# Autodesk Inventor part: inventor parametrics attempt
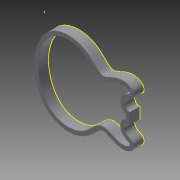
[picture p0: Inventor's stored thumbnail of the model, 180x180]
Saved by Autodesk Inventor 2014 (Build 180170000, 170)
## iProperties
Created: 2015-02
Part Number: inventor parametrics attempt
Material: Generic
Document SubType Name: Modeling
Designer: 11084370
Density: 1 g/cm^3
Appearance: Default
Author: 11084370
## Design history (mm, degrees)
sketch "Sketch1"
  geometry: L1 (-473.76, -224.836)-(-469.826, -225.36); L2 (-469.826, -225.36)-(-462.898, -226.026); L3 (-462.898, -226.026)-(-453.887, -232.464); L4 (-453.887, -232.464)-(-448.305, -241.852); L5 (-448.305, -241.852)-(-447.134, -252.797); L6 (-447.134, -252.797)-(-450.098, -262.975); L7 (-450.098, -262.975)-(-457.24, -271.275); L8 (-457.24, -271.275)-(-466.686, -277.144); L9 (-466.686, -277.144)-(-477.1, -282.087); L10 (-477.1, -282.087)-(-486.72, -288.007); L11 (-486.72, -288.007)-(-494.372, -297.815); L12 (-494.372, -297.815)-(-495.528, -309.852); L13 (-495.528, -309.852)-(-492.092, -320.168); L14 (-492.092, -320.168)-(-486.303, -328.282); L15 (-486.303, -328.282)-(-478.519, -334.425); L16 (-478.519, -334.425)-(-468.938, -339.86); L17 (-468.938, -339.86)-(-456.567, -344.08); L18 (-456.567, -344.08)-(-440.787, -345.448); L19 (-440.787, -345.448)-(-423.43, -344.051); L20 (-423.43, -344.051)-(-406.094, -339.2); L21 (-406.094, -339.2)-(-390.544, -333.851); L22 (-390.544, -333.851)-(-376.137, -326.583); L23 (-376.137, -326.583)-(-363.005, -320.471); L24 (-363.005, -320.471)-(-350.266, -316.029); L25 (-350.266, -316.029)-(-338.697, -315.676); L26 (-338.697, -315.676)-(-327.006, -320.051); L27 (-327.006, -320.051)-(-315.03, -329.645); L28 (-315.03, -329.645)-(-302.723, -341.713); L29 (-302.723, -341.713)-(-288.281, -355.198); L30 (-288.281, -355.198)-(-270.722, -371.083); L31 (-270.722, -371.083)-(-243.358, -389.243); L32 (-243.358, -389.243)-(-208.387, -401.659); L33 (-208.387, -401.659)-(-168.798, -405.883); L34 (-168.798, -405.883)-(-127.248, -400.725); L35 (-127.248, -400.725)-(-86.816, -383.553); L36 (-86.816, -383.553)-(-57.035, -357.48); L37 (-57.035, -357.48)-(-31.631, -323.096); L38 (-31.631, -323.096)-(-13.269, -284.023); L39 (-13.269, -284.023)-(-4.091, -242.624); L40 (-4.091, -242.624)-(0.186, -215.661); L41 (0.186, -215.661)-(0.032, -201.712); L42 (0.032, -201.712)-(-0.001, -196.867); L43 (-0.001, -196.867)-(0.032, -192.316); L44 (0.032, -192.316)-(0.186, -178.367); L45 (0.186, -178.367)-(-4.091, -151.404); L46 (-4.091, -151.404)-(-13.269, -110.005); L47 (-13.269, -110.005)-(-31.631, -70.932); L48 (-31.631, -70.932)-(-57.035, -36.548); L49 (-57.035, -36.548)-(-86.816, -10.475); L50 (-86.816, -10.475)-(-127.248, 6.697); L51 (-127.248, 6.697)-(-168.798, 11.855); L52 (-168.798, 11.855)-(-208.387, 7.63); L53 (-208.387, 7.63)-(-243.358, -4.785); L54 (-243.358, -4.785)-(-270.722, -22.945); L55 (-270.722, -22.945)-(-288.281, -38.83); L56 (-288.281, -38.83)-(-302.723, -52.315); L57 (-302.723, -52.315)-(-315.03, -64.383); L58 (-315.03, -64.383)-(-327.006, -73.977); L59 (-327.006, -73.977)-(-338.697, -78.353); L60 (-338.697, -78.353)-(-350.266, -77.999); L61 (-350.266, -77.999)-(-363.005, -73.557); L62 (-363.005, -73.557)-(-376.137, -67.445); L63 (-376.137, -67.445)-(-390.544, -60.177); L64 (-390.544, -60.177)-(-406.094, -54.828)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; 1 further point
  constraints: 2 end point, 1 vertical, 2 other
extrude "Extrusion1" new body sketch "Sketch1" distance "d0" = 50; taper "d1" = 0 deg
sketch "Sketch2"
  geometry: L1 (473.76, 169.192)-(473.76, 224.836) reference; L2 (453.76, 209.145)-(453.76, 184.883); 1 further point
  constraints: 2 end point, 2 vertical alignment, 1 parallel, 2 other
  dimensions: "d2" = 20 distance between parallel lines of L1 L2
extrude "Extrusion2" cut sketch "Sketch2" distance "d3" = 50; taper "d4" = 0 deg
sketch "Sketch3"
  geometry: L1 (453.76, 209.145)-(453.76, 184.883) reference; L2 (473.76, 169.192)-(473.76, 224.836) reference; L3 (99.12, 387.715)-(98.391, 364.387); L4 (89.038, 382.116)-(88.331, 357.383); L5 (85.028, 379.578)-(84.331, 354.16); L6 (74.939, 372.301)-(74.271, 344.776); L7 (70.926, 369.018)-(70.271, 340.457); L8 (60.829, 359.637)-(60.211, 327.789); L9 (56.812, 355.399)-(56.211, 321.956); L10 (46.704, 343.187)-(46.151, 304.92); L11 (42.682, 337.639)-(42.151, 296.913); L12 (32.558, 321.683)-(32.091, 271.357); L13 (28.53, 314.381)-(28.091, 257.174); L14 (18.382, 292.382)-(18.031, 102.536); L15 (14.339, 281.399)-(14.031, 113.546); L16 (4.119, 240.915)-(3.971, 153.901); L17 (113.205, 393.934)-(112.451, 371.939); L18 (117.211, 395.402)-(116.451, 373.693); L19 (127.283, 398.562)-(126.511, 377.439); L20 (131.287, 399.616)-(130.511, 378.684); L21 (145.359, 402.467)-(144.571, 382.044); L22 (155.424, 403.724)-(154.631, 383.538); L23 (159.425, 404.048)-(158.631, 383.93); L24 (183.425, 403.938)-(182.631, 383.938); L25 (187.423, 403.579)-(186.631, 383.55); L26 (197.418, 402.25)-(196.631, 382.09); L27 (201.415, 401.544)-(200.631, 381.306); L28 (211.407, 399.333)-(210.631, 378.829); L29 (215.403, 398.264)-(214.631, 377.623); L30 (225.39, 395.11)-(224.631, 374.027); L31 (229.384, 393.646)-(228.631, 372.341); L32 (239.368, 389.436)-(238.631, 367.435); L33 (243.36, 387.518)-(242.631, 365.172); L34 (253.339, 382.075)-(252.631, 358.719); L35 (257.329, 379.627)-(256.631, 355.807); L36 (267.302, 372.796)-(266.631, 347.675); L37 (271.29, 369.767)-(270.631, 344.141); L38 (281.258, 361.454)-(280.631, 334.962); L39 (285.244, 357.895)-(284.631, 331.214); L40 (295.207, 348.715)-(294.631, 321.674); L41 (299.193, 344.971)-(298.631, 317.924); L42 (309.215, 335.407)-(308.691, 309.245); L43 (313.2, 331.699)-(312.691, 306.298); L44 (323.167, 323.381)-(322.691, 300.578); L45 (327.157, 320.769)-(326.691, 298.947); L46 (337.141, 316.679)-(336.691, 296.452); L47 (341.139, 316.081)-(340.691, 296.068); L48 (351.142, 316.836)-(350.691, 296.475); L49 (355.146, 317.876)-(354.691, 297.147); L50 (365.161, 321.635)-(364.691, 299.967); L51 (368.818, 323.238)-(368.691, 301.467); L52 (378.823, 327.983)-(378.691, 305.757); L53 (382.825, 329.933)-(382.691, 307.632); L54 (392.83, 334.39)-(392.691, 312.483); L55 (396.831, 335.913)-(396.691, 314.326); L56 (406.835, 339.252)-(406.691, 318.184); L57 (410.836, 340.451)-(410.691, 319.501); L58 (420.839, 342.964)-(420.691, 322.409); L59 (424.84, 343.701)-(424.769, 323.353); L60 (434.844, 344.792)-(434.774, 324.745); L61 (438.844, 344.943)-(438.775, 324.937); L62 (448.843, 344.617)-(448.773, 324.517); L63 (452.841, 344.149)-(452.771, 323.853); L64 (462.833, 341.824)-(462.759, 320.246)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; 1 further point
  constraints: 314 end point, 310 other
body "Solid1"
other parameters: "d13" = 4, "d17" = 10.06, "d24" = 10.06 (= d17)
